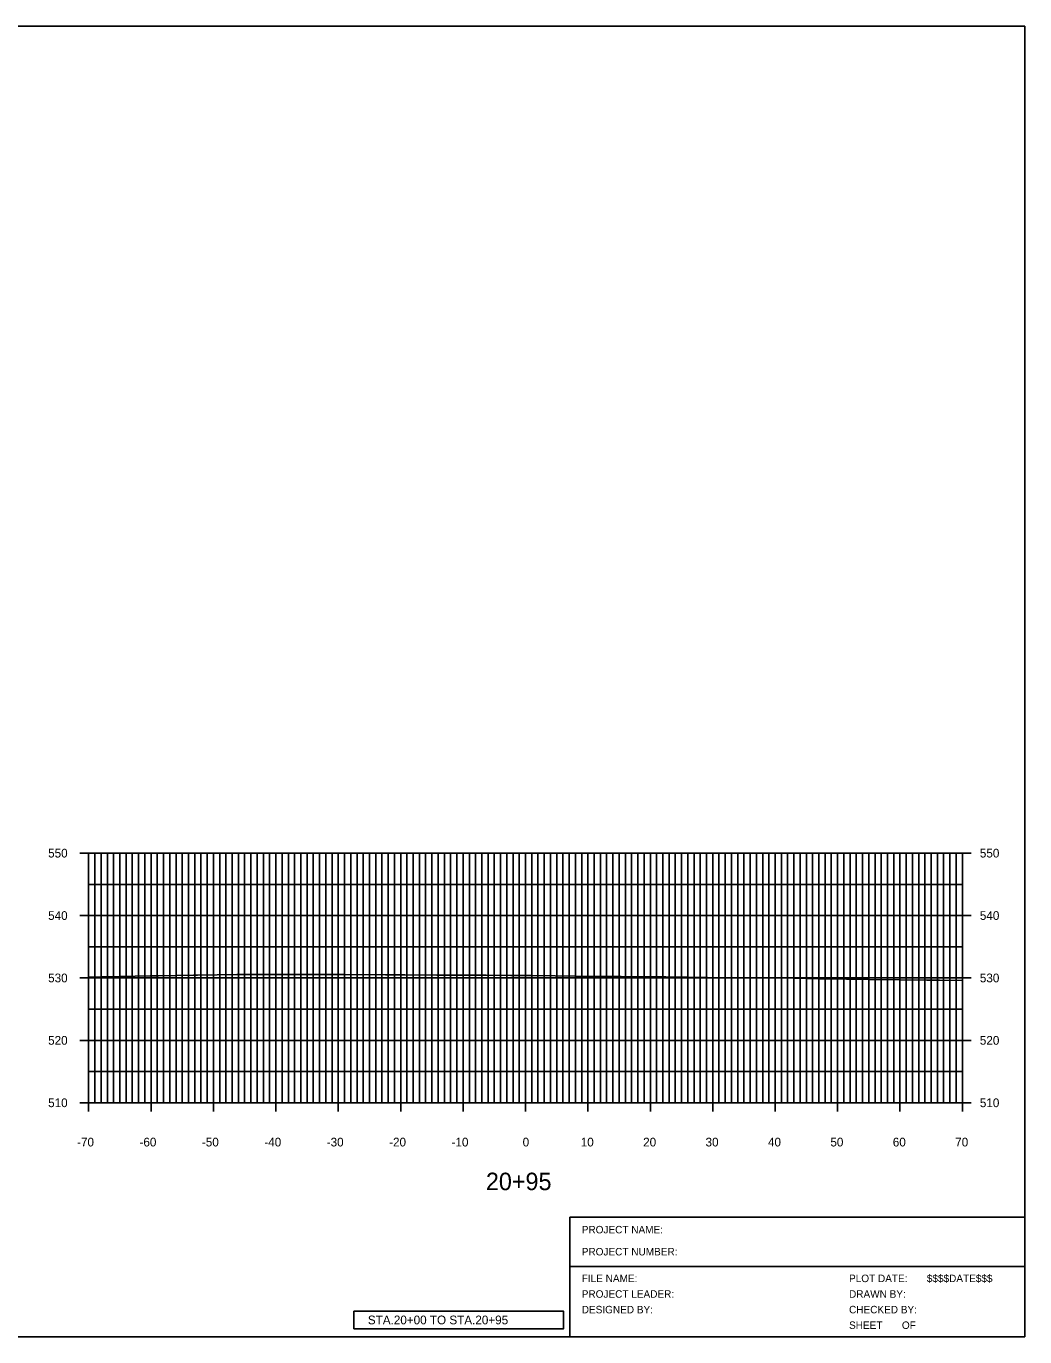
# Model space of a CAD drawing. Extents: x 1509063 to 1512863, y 401160 to 402918.
# Drawn here: x 1510410.9 to 1510570.9, y 402707.9 to 402917.9 of the extents above; entities that cross this region are included whole.
import ezdxf

# ---------------------------------------------------------------- set-up
doc = ezdxf.new("R2010")
doc.units = 0
for name, color, linetype in [('NBL1', 7, 'Continuous'), ('XAX_P', 7, 'Continuous'), ('XAXTIC_P', 7, 'Continuous'), ('XAXTXT_P_T', 7, 'Continuous'), ('XFRAME_P', 7, 'Continuous'), ('XGL_P', 7, 'Continuous'), ('XSLOG', 7, 'Continuous')]:
    doc.layers.add(name, color=color, linetype=linetype)

msp = doc.modelspace()

# ---------------------------------------------------------------- linework, layer by layer
at = {"layer": 'NBL1'}
for p, q in [((1510497.99, 402727.08), (1510570.91, 402727.08)), ((1510497.99, 402707.91), (1510497.99, 402727.08)), ((1510497.99, 402719.16), (1510570.91, 402719.16))]:
    msp.add_line(p, q, dxfattribs=at)
msp.add_lwpolyline([(1510570.91, 402707.91), (1510250.91, 402707.91), (1510250.91, 402917.91), (1510570.91, 402917.91)], close=True, dxfattribs=at)
at = {"layer": 'XAX_P'}
for p, q in [((1510420.91, 402745.41), (1510420.91, 402785.41)), ((1510490.91, 402745.41), (1510490.91, 402785.41)), ((1510560.91, 402745.41), (1510560.91, 402785.41)), ((1510420.91, 402745.41), (1510560.91, 402745.41))]:
    msp.add_line(p, q, dxfattribs=at)
at = {"layer": 'XAXTIC_P'}
for p, q in [((1510419.51, 402785.41), (1510422.31, 402785.41)), ((1510489.51, 402785.41), (1510492.31, 402785.41)), ((1510562.31, 402785.41), (1510559.51, 402785.41)), ((1510419.51, 402775.41), (1510422.31, 402775.41)), ((1510489.51, 402775.41), (1510492.31, 402775.41)), ((1510562.31, 402775.41), (1510559.51, 402775.41)), ((1510419.51, 402765.41), (1510422.31, 402765.41)), ((1510489.51, 402765.41), (1510492.31, 402765.41)), ((1510562.31, 402765.41), (1510559.51, 402765.41)), ((1510419.51, 402755.41), (1510422.31, 402755.41)), ((1510489.51, 402755.41), (1510492.31, 402755.41)), ((1510562.31, 402755.41), (1510559.51, 402755.41)), ((1510420.91, 402744.01), (1510420.91, 402746.81)), ((1510430.91, 402744.01), (1510430.91, 402746.81)), ((1510440.91, 402744.01), (1510440.91, 402746.81)), ((1510450.91, 402744.01), (1510450.91, 402746.81)), ((1510460.91, 402744.01), (1510460.91, 402746.81)), ((1510470.91, 402744.01), (1510470.91, 402746.81)), ((1510480.91, 402744.01), (1510480.91, 402746.81)), ((1510490.91, 402744.01), (1510490.91, 402746.81)), ((1510500.91, 402744.01), (1510500.91, 402746.81)), ((1510510.91, 402744.01), (1510510.91, 402746.81)), ((1510520.91, 402744.01), (1510520.91, 402746.81)), ((1510530.91, 402744.01), (1510530.91, 402746.81)), ((1510540.91, 402744.01), (1510540.91, 402746.81)), ((1510550.91, 402744.01), (1510550.91, 402746.81)), ((1510560.91, 402744.01), (1510560.91, 402746.81)), ((1510419.51, 402745.41), (1510422.31, 402745.41)), ((1510489.51, 402745.41), (1510492.31, 402745.41)), ((1510562.31, 402745.41), (1510559.51, 402745.41))]:
    msp.add_line(p, q, dxfattribs=at)
at = {"layer": 'XFRAME_P'}
msp.add_lwpolyline([(1510463.41, 402712.01), (1510497.01, 402712.01), (1510497.01, 402709.21), (1510463.41, 402709.21)], close=True, dxfattribs=at)
at = {"layer": 'XGL_P'}
for p, q in [((1510420.91, 402785.41), (1510560.91, 402785.41)), ((1510420.91, 402745.41), (1510420.91, 402785.41)), ((1510421.91, 402745.41), (1510421.91, 402785.41)), ((1510422.91, 402745.41), (1510422.91, 402785.41)), ((1510423.91, 402745.41), (1510423.91, 402785.41)), ((1510424.91, 402745.41), (1510424.91, 402785.41)), ((1510425.91, 402745.41), (1510425.91, 402785.41)), ((1510426.91, 402745.41), (1510426.91, 402785.41)), ((1510427.91, 402745.41), (1510427.91, 402785.41)), ((1510428.91, 402745.41), (1510428.91, 402785.41)), ((1510429.91, 402745.41), (1510429.91, 402785.41)), ((1510430.91, 402745.41), (1510430.91, 402785.41)), ((1510431.91, 402745.41), (1510431.91, 402785.41)), ((1510432.91, 402745.41), (1510432.91, 402785.41)), ((1510433.91, 402745.41), (1510433.91, 402785.41)), ((1510434.91, 402745.41), (1510434.91, 402785.41)), ((1510435.91, 402745.41), (1510435.91, 402785.41)), ((1510436.91, 402745.41), (1510436.91, 402785.41)), ((1510437.91, 402745.41), (1510437.91, 402785.41)), ((1510438.91, 402745.41), (1510438.91, 402785.41)), ((1510439.91, 402745.41), (1510439.91, 402785.41)), ((1510440.91, 402745.41), (1510440.91, 402785.41)), ((1510441.91, 402745.41), (1510441.91, 402785.41)), ((1510442.91, 402745.41), (1510442.91, 402785.41)), ((1510443.91, 402745.41), (1510443.91, 402785.41)), ((1510444.91, 402745.41), (1510444.91, 402785.41)), ((1510445.91, 402745.41), (1510445.91, 402785.41)), ((1510446.91, 402745.41), (1510446.91, 402785.41)), ((1510447.91, 402745.41), (1510447.91, 402785.41)), ((1510448.91, 402745.41), (1510448.91, 402785.41)), ((1510449.91, 402745.41), (1510449.91, 402785.41)), ((1510450.91, 402745.41), (1510450.91, 402785.41)), ((1510451.91, 402745.41), (1510451.91, 402785.41)), ((1510452.91, 402745.41), (1510452.91, 402785.41)), ((1510453.91, 402745.41), (1510453.91, 402785.41)), ((1510454.91, 402745.41), (1510454.91, 402785.41)), ((1510455.91, 402745.41), (1510455.91, 402785.41)), ((1510456.91, 402745.41), (1510456.91, 402785.41)), ((1510457.91, 402745.41), (1510457.91, 402785.41)), ((1510458.91, 402745.41), (1510458.91, 402785.41)), ((1510459.91, 402745.41), (1510459.91, 402785.41)), ((1510460.91, 402745.41), (1510460.91, 402785.41)), ((1510461.91, 402745.41), (1510461.91, 402785.41)), ((1510462.91, 402745.41), (1510462.91, 402785.41)), ((1510463.91, 402745.41), (1510463.91, 402785.41)), ((1510464.91, 402745.41), (1510464.91, 402785.41)), ((1510465.91, 402745.41), (1510465.91, 402785.41)), ((1510466.91, 402745.41), (1510466.91, 402785.41)), ((1510467.91, 402745.41), (1510467.91, 402785.41)), ((1510468.91, 402745.41), (1510468.91, 402785.41)), ((1510469.91, 402745.41), (1510469.91, 402785.41)), ((1510470.91, 402745.41), (1510470.91, 402785.41)), ((1510471.91, 402745.41), (1510471.91, 402785.41)), ((1510472.91, 402745.41), (1510472.91, 402785.41)), ((1510473.91, 402745.41), (1510473.91, 402785.41)), ((1510474.91, 402745.41), (1510474.91, 402785.41)), ((1510475.91, 402745.41), (1510475.91, 402785.41)), ((1510476.91, 402745.41), (1510476.91, 402785.41)), ((1510477.91, 402745.41), (1510477.91, 402785.41)), ((1510478.91, 402745.41), (1510478.91, 402785.41)), ((1510479.91, 402745.41), (1510479.91, 402785.41)), ((1510480.91, 402745.41), (1510480.91, 402785.41)), ((1510481.91, 402745.41), (1510481.91, 402785.41)), ((1510482.91, 402745.41), (1510482.91, 402785.41)), ((1510483.91, 402745.41), (1510483.91, 402785.41)), ((1510484.91, 402745.41), (1510484.91, 402785.41)), ((1510485.91, 402745.41), (1510485.91, 402785.41)), ((1510486.91, 402745.41), (1510486.91, 402785.41)), ((1510487.91, 402745.41), (1510487.91, 402785.41)), ((1510488.91, 402745.41), (1510488.91, 402785.41)), ((1510489.91, 402745.41), (1510489.91, 402785.41)), ((1510490.91, 402745.41), (1510490.91, 402785.41)), ((1510491.91, 402745.41), (1510491.91, 402785.41)), ((1510492.91, 402745.41), (1510492.91, 402785.41)), ((1510493.91, 402745.41), (1510493.91, 402785.41)), ((1510494.91, 402745.41), (1510494.91, 402785.41)), ((1510495.91, 402745.41), (1510495.91, 402785.41)), ((1510496.91, 402745.41), (1510496.91, 402785.41)), ((1510497.91, 402745.41), (1510497.91, 402785.41)), ((1510498.91, 402745.41), (1510498.91, 402785.41)), ((1510499.91, 402745.41), (1510499.91, 402785.41)), ((1510500.91, 402745.41), (1510500.91, 402785.41)), ((1510501.91, 402745.41), (1510501.91, 402785.41)), ((1510502.91, 402745.41), (1510502.91, 402785.41)), ((1510503.91, 402745.41), (1510503.91, 402785.41)), ((1510504.91, 402745.41), (1510504.91, 402785.41)), ((1510505.91, 402745.41), (1510505.91, 402785.41)), ((1510506.91, 402745.41), (1510506.91, 402785.41)), ((1510507.91, 402745.41), (1510507.91, 402785.41)), ((1510508.91, 402745.41), (1510508.91, 402785.41)), ((1510509.91, 402745.41), (1510509.91, 402785.41)), ((1510510.91, 402745.41), (1510510.91, 402785.41)), ((1510511.91, 402745.41), (1510511.91, 402785.41)), ((1510512.91, 402745.41), (1510512.91, 402785.41)), ((1510513.91, 402745.41), (1510513.91, 402785.41)), ((1510514.91, 402745.41), (1510514.91, 402785.41)), ((1510515.91, 402745.41), (1510515.91, 402785.41)), ((1510516.91, 402745.41), (1510516.91, 402785.41)), ((1510517.91, 402745.41), (1510517.91, 402785.41)), ((1510518.91, 402745.41), (1510518.91, 402785.41)), ((1510519.91, 402745.41), (1510519.91, 402785.41)), ((1510520.91, 402745.41), (1510520.91, 402785.41)), ((1510521.91, 402745.41), (1510521.91, 402785.41)), ((1510522.91, 402745.41), (1510522.91, 402785.41)), ((1510523.91, 402745.41), (1510523.91, 402785.41)), ((1510524.91, 402745.41), (1510524.91, 402785.41)), ((1510525.91, 402745.41), (1510525.91, 402785.41)), ((1510526.91, 402745.41), (1510526.91, 402785.41)), ((1510527.91, 402745.41), (1510527.91, 402785.41)), ((1510528.91, 402745.41), (1510528.91, 402785.41)), ((1510529.91, 402745.41), (1510529.91, 402785.41)), ((1510530.91, 402745.41), (1510530.91, 402785.41)), ((1510531.91, 402745.41), (1510531.91, 402785.41)), ((1510532.91, 402745.41), (1510532.91, 402785.41)), ((1510533.91, 402745.41), (1510533.91, 402785.41)), ((1510534.91, 402745.41), (1510534.91, 402785.41)), ((1510535.91, 402745.41), (1510535.91, 402785.41)), ((1510536.91, 402745.41), (1510536.91, 402785.41)), ((1510537.91, 402745.41), (1510537.91, 402785.41)), ((1510538.91, 402745.41), (1510538.91, 402785.41)), ((1510539.91, 402745.41), (1510539.91, 402785.41)), ((1510540.91, 402745.41), (1510540.91, 402785.41)), ((1510541.91, 402745.41), (1510541.91, 402785.41)), ((1510542.91, 402745.41), (1510542.91, 402785.41)), ((1510543.91, 402745.41), (1510543.91, 402785.41)), ((1510544.91, 402745.41), (1510544.91, 402785.41)), ((1510545.91, 402745.41), (1510545.91, 402785.41)), ((1510546.91, 402745.41), (1510546.91, 402785.41)), ((1510547.91, 402745.41), (1510547.91, 402785.41)), ((1510548.91, 402745.41), (1510548.91, 402785.41)), ((1510549.91, 402745.41), (1510549.91, 402785.41)), ((1510550.91, 402745.41), (1510550.91, 402785.41)), ((1510551.91, 402745.41), (1510551.91, 402785.41)), ((1510552.91, 402745.41), (1510552.91, 402785.41)), ((1510553.91, 402745.41), (1510553.91, 402785.41)), ((1510554.91, 402745.41), (1510554.91, 402785.41)), ((1510555.91, 402745.41), (1510555.91, 402785.41)), ((1510556.91, 402745.41), (1510556.91, 402785.41)), ((1510557.91, 402745.41), (1510557.91, 402785.41)), ((1510558.91, 402745.41), (1510558.91, 402785.41)), ((1510559.91, 402745.41), (1510559.91, 402785.41)), ((1510560.91, 402745.41), (1510560.91, 402785.41)), ((1510420.91, 402780.41), (1510560.91, 402780.41)), ((1510420.91, 402775.41), (1510560.91, 402775.41)), ((1510420.91, 402770.41), (1510560.91, 402770.41)), ((1510420.91, 402765.41), (1510560.91, 402765.41)), ((1510420.91, 402760.41), (1510560.91, 402760.41)), ((1510420.91, 402755.41), (1510560.91, 402755.41)), ((1510420.91, 402750.41), (1510560.91, 402750.41)), ((1510420.91, 402745.41), (1510560.91, 402745.41))]:
    msp.add_line(p, q, dxfattribs=at)
at = {"layer": 'XSLOG'}
msp.add_lwpolyline([(1510420.91, 402765.56), (1510423.08, 402765.6), (1510425.98, 402765.67), (1510430.75, 402765.75), (1510432.1, 402765.76), (1510437.72, 402765.85), (1510438.37, 402765.85), (1510444.66, 402765.96), (1510444.73, 402765.96), (1510445.54, 402765.97), (1510450.64, 402765.99), (1510451.16, 402765.99), (1510451.95, 402765.98), (1510460, 402765.94), (1510462, 402765.94), (1510468.5, 402765.91), (1510471.57, 402765.9), (1510476.7, 402765.88), (1510480.73, 402765.87), (1510484.62, 402765.85), (1510488.54, 402765.82), (1510491.8, 402765.78), (1510495.68, 402765.74), (1510499, 402765.7), (1510502.83, 402765.67), (1510506.21, 402765.62), (1510510, 402765.59), (1510513.37, 402765.57), (1510516.81, 402765.52), (1510520.06, 402765.5), (1510523.77, 402765.45), (1510526.89, 402765.43), (1510529.89, 402765.41), (1510533.86, 402765.35), (1510537.86, 402765.29), (1510542.34, 402765.23), (1510545.85, 402765.18), (1510550.79, 402765.11), (1510555.22, 402765.07), (1510557.22, 402765.04), (1510560.91, 402765)], dxfattribs=at)

# ---------------------------------------------------------------- texts
at = {"layer": 'NBL1'}
for s, p in [('PROJECT NAME:', (1510499.92, 402724.48)), ('PROJECT NUMBER:', (1510499.92, 402720.95)), ('FILE NAME:', (1510499.92, 402716.67)), ('PLOT DATE:', (1510542.75, 402716.67)), ('$$$$DATE$$$', (1510555.21, 402716.67)), ('PROJECT LEADER:', (1510499.92, 402714.17)), ('DRAWN BY:', (1510542.75, 402714.17)), ('DESIGNED BY:', (1510499.92, 402711.67)), ('CHECKED BY:', (1510542.75, 402711.67)), ('SHEET       OF', (1510542.75, 402709.17))]:
    msp.add_text(s, height=1.2, rotation=360, dxfattribs=at).set_placement(p)
at = {"layer": 'XAXTXT_P_T'}
for s, height, p in [('550', 1.4, (1510414.42, 402784.71)), ('550', 1.4, (1510563.71, 402784.71)), ('540', 1.4, (1510414.42, 402774.71)), ('540', 1.4, (1510563.71, 402774.71)), ('530', 1.4, (1510414.42, 402764.71)), ('530', 1.4, (1510563.71, 402764.71)), ('520', 1.4, (1510414.42, 402754.71)), ('520', 1.4, (1510563.71, 402754.71)), ('510', 1.4, (1510414.42, 402744.71)), ('510', 1.4, (1510563.71, 402744.71)), ('-70', 1.4, (1510419.06, 402738.41)), ('-60', 1.4, (1510429.06, 402738.41)), ('-50', 1.4, (1510439.06, 402738.41)), ('-40', 1.4, (1510449.06, 402738.41)), ('-30', 1.4, (1510459.06, 402738.41)), ('-20', 1.4, (1510469.06, 402738.41)), ('-10', 1.4, (1510479.06, 402738.41)), ('0', 1.4, (1510490.45, 402738.41)), ('10', 1.4, (1510499.76, 402738.41)), ('20', 1.4, (1510509.76, 402738.41)), ('30', 1.4, (1510519.76, 402738.41)), ('40', 1.4, (1510529.76, 402738.41)), ('50', 1.4, (1510539.76, 402738.41)), ('60', 1.4, (1510549.76, 402738.41)), ('70', 1.4, (1510559.76, 402738.41)), ('20+95', 2.8, (1510484.56, 402731.41))]:
    msp.add_text(s, height=height, dxfattribs=at).set_placement(p)
at = {"layer": 'XFRAME_P'}
msp.add_text('STA.20+00 TO STA.20+95', height=1.4, dxfattribs=at).set_placement((1510465.65, 402709.91))

doc.saveas('drawing.dxf')
